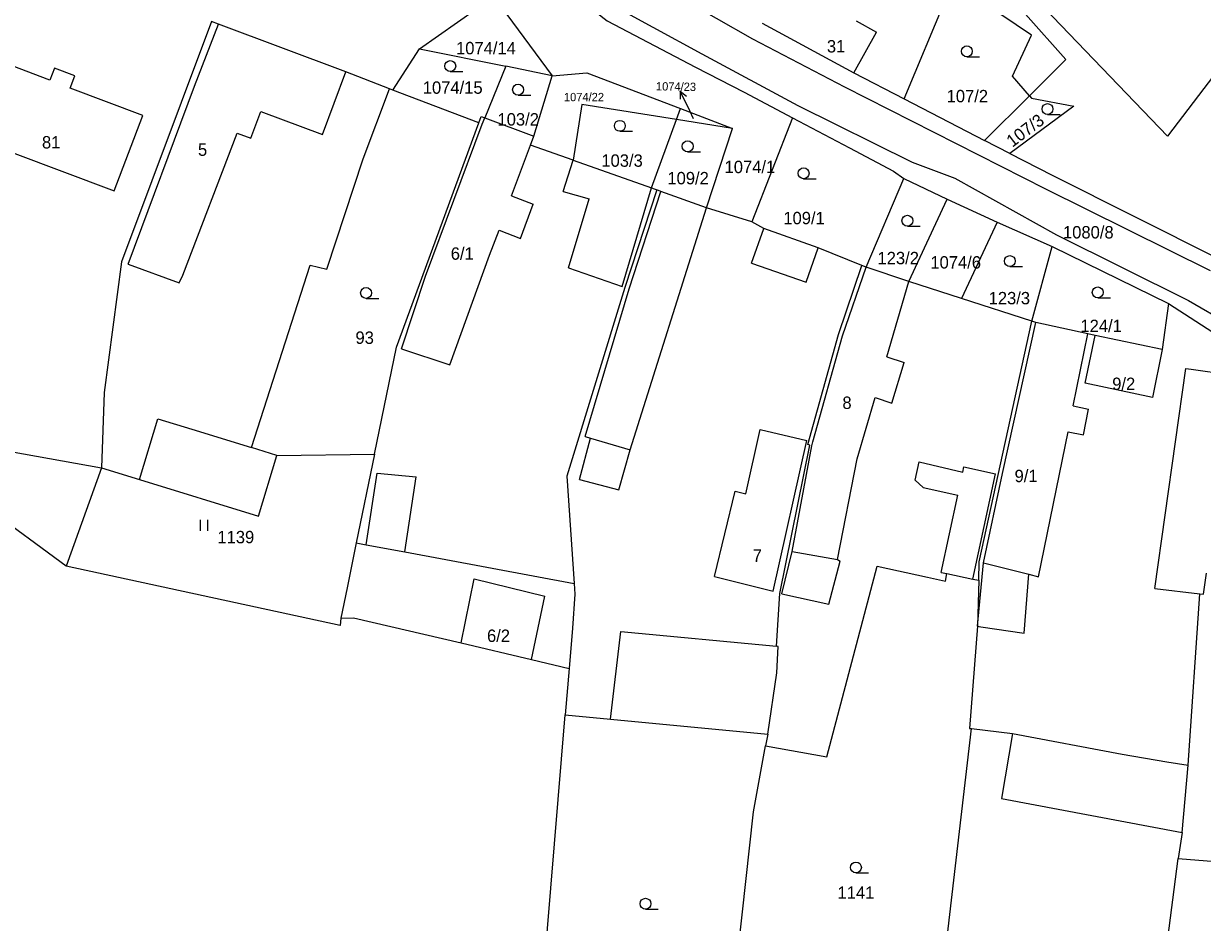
# Model space of a CAD drawing. Extents: x -746176 to -739709, y -1128407 to -1124482.
# Drawn here: x -742377 to -742215.1, y -1126240.2 to -1126116.8 of the extents above; entities that cross this region are included whole.
import ezdxf

# ---------------------------------------------------------------- set-up
doc = ezdxf.new("R2010")
doc.units = 0
for name, color, linetype in [('Hranice parcel', 7, 'Continuous'), ('Parcelní čísla', 7, 'Continuous'), ('Pop  PČ popisy', 7, 'Continuous'), ('Vnitřní kresba', 7, 'Continuous'), ('Značky kultur', 7, 'Continuous')]:
    doc.layers.add(name, color=color, linetype=linetype)

msp = doc.modelspace()

# ---------------------------------------------------------------- linework, layer by layer
at = {"layer": 'Hranice parcel'}
for p, q in [((-742256.06, -1126127.14), (-742249.36, -1126111.09)), ((-742326.25, -1126125.97), (-742322.59, -1126120.3)), ((-742322.59, -1126120.3), (-742310.73, -1126122.68)), ((-742310.73, -1126122.68), (-742313.65, -1126129.74)), ((-742304.4, -1126124.01), (-742310.73, -1126122.68)), ((-742233.84, -1126121.75), (-742238.85, -1126126.73)), ((-742306.9, -1126132.3), (-742304.4, -1126124.01)), ((-742238.85, -1126126.73), (-742241.16, -1126124.04)), ((-742326.25, -1126125.97), (-742326.7, -1126125.8)), ((-742314.45, -1126130.46), (-742326.25, -1126125.97)), ((-742256.06, -1126127.14), (-742245.01, -1126132.86)), ((-742245.01, -1126132.86), (-742238.85, -1126126.73)), ((-742238.85, -1126126.73), (-742238.56, -1126127.06)), ((-742300.31, -1126127.94), (-742301.49, -1126135.55)), ((-742287.33, -1126129.99), (-742300.31, -1126127.94)), ((-742287.33, -1126129.99), (-742286.78, -1126128.49)), ((-742286.78, -1126128.49), (-742279.63, -1126131.21)), ((-742313.65, -1126129.74), (-742306.9, -1126132.3)), ((-742290.74, -1126139.38), (-742287.33, -1126129.99)), ((-742279.63, -1126131.21), (-742287.33, -1126129.99)), ((-742271.38, -1126129.77), (-742276.96, -1126144.02)), ((-742283.2, -1126142.1), (-742279.63, -1126131.21)), ((-742241.52, -1126134.66), (-742245.01, -1126132.86)), ((-742301.49, -1126135.55), (-742290.74, -1126139.38)), ((-742261.26, -1126150.24), (-742256.1, -1126138.11)), ((-742256.1, -1126138.11), (-742250.15, -1126140.92)), ((-742290.74, -1126139.38), (-742290.03, -1126139.66)), ((-742276.96, -1126144.02), (-742283.2, -1126142.1)), ((-742255.42, -1126152.21), (-742250.15, -1126140.92)), ((-742250.15, -1126140.92), (-742243.28, -1126144.09)), ((-742243.28, -1126144.09), (-742248.16, -1126154.55)), ((-742243.28, -1126144.09), (-742235.72, -1126147.41)), ((-742238.52, -1126157.67), (-742235.72, -1126147.41)), ((-742235.72, -1126147.41), (-742219.77, -1126155.24)), ((-742261.26, -1126150.24), (-742261.84, -1126150.05)), ((-742255.42, -1126152.21), (-742261.26, -1126150.24)), ((-742248.16, -1126154.55), (-742255.42, -1126152.21)), ((-742238.52, -1126157.67), (-742248.16, -1126154.55)), ((-742219.77, -1126155.24), (-742220.62, -1126161.55)), ((-742219.77, -1126155.24), (-742210.43, -1126161.29)), ((-742220.62, -1126161.55), (-742229.8, -1126159.63)), ((-742408.55, -1126170.19), (-742366.28, -1126177.8)), ((-742342.18, -1126176.09), (-742328.77, -1126175.93)), ((-742328.77, -1126175.93), (-742331.28, -1126188.11)), ((-742366.28, -1126177.8), (-742371.13, -1126191.3)), ((-742331.28, -1126188.11), (-742332.55, -1126194.28)), ((-742332.55, -1126194.28), (-742333.4, -1126198.44)), ((-742302.07, -1126205.33), (-742302.59, -1126211.7)), ((-742274.79, -1126214.34), (-742275.09, -1126215.95)), ((-742253.45, -1126270.36), (-742246.8, -1126213.59)), ((-742217.86, -1126227.84), (-742218.41, -1126231.43)), ((-742226.78, -1126295.24), (-742218.41, -1126231.43)), ((-742218.41, -1126231.43), (-742213.31, -1126231.82))]:
    msp.add_line(p, q, dxfattribs=at)
for points in [[(-742322.88, -1126080.92), (-742314.75, -1126099.48), (-742306.74, -1126108.67), (-742296.81, -1126116.44), (-742284.71, -1126122.79), (-742278, -1126126.23), (-742271.38, -1126129.77)], [(-742226.91, -1126088.92), (-742220.21, -1126088.74), (-742209.67, -1126089.51), (-742205.42, -1126090.21), (-742203.87, -1126091.46), (-742201.62, -1126095.17), (-742208.44, -1126114.62), (-742212.86, -1126123.04), (-742219.9, -1126132.27), (-742250.27, -1126100.63), (-742249.53, -1126099.74), (-742247.13, -1126097.23), (-742241.64, -1126096.04), (-742237.53, -1126090.17), (-742226.91, -1126088.92)], [(-742253.64, -1126102.41), (-742239.39, -1126115.53), (-742233.84, -1126121.75)], [(-742241.16, -1126124.04), (-742238.58, -1126118.41), (-742249.36, -1126111.09)], [(-742322.59, -1126120.3), (-742314.77, -1126114.82), (-742311.38, -1126114.53), (-742304.4, -1126124.01)], [(-742351.14, -1126116.55), (-742363.54, -1126149.51), (-742365.92, -1126167.47), (-742366.28, -1126177.8)], [(-742326.7, -1126125.8), (-742332.7, -1126123.44), (-742350.2, -1126116.9), (-742351.14, -1126116.55)], [(-742275.57, -1126116.75), (-742262.95, -1126123.57), (-742256.06, -1126127.14)], [(-742360.61, -1126129.44), (-742370.56, -1126125.67), (-742369.93, -1126124), (-742372.74, -1126122.95), (-742373.37, -1126124.6), (-742381.46, -1126121.54), (-742385.41, -1126131.94), (-742364.54, -1126139.8), (-742360.61, -1126129.44)], [(-742304.4, -1126124.01), (-742299.64, -1126123.59), (-742286.78, -1126128.49)], [(-742342.18, -1126176.09), (-742345.69, -1126175.02), (-742337.62, -1126150), (-742335.33, -1126150.55), (-742330.35, -1126135.4), (-742326.7, -1126125.8)], [(-742238.56, -1126127.06), (-742232.76, -1126128.14), (-742241.52, -1126134.66)], [(-742328.77, -1126175.93), (-742325.75, -1126161.24), (-742314.45, -1126130.46)], [(-742314.45, -1126130.46), (-742314.12, -1126129.57), (-742313.65, -1126129.74)], [(-742271.38, -1126129.77), (-742263.55, -1126133.89), (-742257.51, -1126137.07), (-742256.1, -1126138.11)], [(-742301.49, -1126135.55), (-742307.36, -1126133.52), (-742306.9, -1126132.3)], [(-742241.52, -1126134.66), (-742235.74, -1126137.65), (-742212.93, -1126149.05), (-742177.34, -1126171.16)], [(-742290.03, -1126139.66), (-742294.39, -1126153.07), (-742302.36, -1126178.95), (-742301.38, -1126193.67)], [(-742283.2, -1126142.1), (-742289.47, -1126139.88), (-742290.03, -1126139.66)], [(-742261.84, -1126150.05), (-742267.85, -1126147.6), (-742275.32, -1126144.93), (-742276.96, -1126144.02)], [(-742274.79, -1126214.34), (-742273.54, -1126205.94), (-742273.34, -1126202.32), (-742273.6, -1126202.3), (-742273.12, -1126195.05), (-742269.02, -1126174.69), (-742269.3, -1126174.61), (-742265.06, -1126159.49), (-742261.84, -1126150.05)], [(-742245.81, -1126193.24), (-742245.74, -1126190.69), (-742238.52, -1126157.67)], [(-742229.8, -1126159.63), (-742230.81, -1126159.4), (-742237.95, -1126157.86), (-742238.52, -1126157.67)], [(-742220.62, -1126161.55), (-742221.93, -1126168.17), (-742231.21, -1126166.16), (-742229.8, -1126159.63)], [(-742366.28, -1126177.8), (-742361.05, -1126179.41), (-742344.7, -1126184.42), (-742342.18, -1126176.09)], [(-742371.13, -1126191.3), (-742382.1, -1126183.23), (-742395.78, -1126181.85), (-742403.65, -1126182.31), (-742424.12, -1126188.09), (-742455.22, -1126201.03)], [(-742331.28, -1126188.11), (-742329.94, -1126188.36), (-742324.62, -1126189.35), (-742301.38, -1126193.67)], [(-742333.4, -1126198.44), (-742333.49, -1126199.45), (-742371.13, -1126191.3)], [(-742275.09, -1126215.95), (-742266.66, -1126217.47), (-742260.87, -1126195.48), (-742259.76, -1126191.3), (-742252.85, -1126192.83), (-742250.39, -1126193.38), (-742250.2, -1126192.33), (-742246.63, -1126193.07), (-742245.81, -1126193.24)], [(-742217.86, -1126227.84), (-742217.03, -1126218.63), (-742215.44, -1126195.1), (-742214.95, -1126195.15), (-742214.53, -1126192.26)], [(-742301.38, -1126193.67), (-742301.28, -1126195.16), (-742301.61, -1126199.8), (-742302.07, -1126205.33)], [(-742245.81, -1126193.24), (-742245.98, -1126199.54), (-742247.06, -1126213.57), (-742246.8, -1126213.59)], [(-742333.4, -1126198.44), (-742331.66, -1126198.39), (-742316.87, -1126201.82), (-742307.21, -1126204.11), (-742302.07, -1126205.33)], [(-742281.72, -1126273.18), (-742307.41, -1126266.17), (-742306.81, -1126260.62), (-742305.51, -1126247.12), (-742302.59, -1126211.7)], [(-742302.59, -1126211.7), (-742296.36, -1126212.29), (-742274.79, -1126214.34)], [(-742246.8, -1126213.59), (-742241.16, -1126214.28), (-742242.7, -1126223.21), (-742217.86, -1126227.84)], [(-742281.72, -1126273.18), (-742280.8, -1126262.02), (-742276.72, -1126225.02), (-742275.09, -1126215.95)]]:
    msp.add_lwpolyline(points, dxfattribs=at)
at = {"layer": 'Pop  PČ popisy'}
for p, q in [((-742286.81, -1126126.09), (-742286.82, -1126127.21)), ((-742285.49, -1126128.79), (-742286.81, -1126126.09)), ((-742286.81, -1126126.09), (-742285.92, -1126126.77)), ((-742284.96, -1126129.91), (-742285.49, -1126128.79))]:
    msp.add_line(p, q, dxfattribs=at)
at = {"layer": 'Vnitřní kresba'}
for p, q in [((-742296.2, -1126107.89), (-742276.88, -1126118.92)), ((-742297.3, -1126113.67), (-742283.82, -1126120.97)), ((-742353.49, -1126125.42), (-742350.2, -1126116.9)), ((-742262.66, -1126116.47), (-742259.87, -1126118.01)), ((-742276.88, -1126118.92), (-742264.25, -1126125.49)), ((-742262.95, -1126123.57), (-742259.87, -1126118.01)), ((-742283.82, -1126120.97), (-742270.64, -1126128.09)), ((-742335.92, -1126132.03), (-742332.7, -1126123.44)), ((-742362.62, -1126149.84), (-742353.49, -1126125.42)), ((-742264.25, -1126125.49), (-742236.63, -1126139.49)), ((-742345.76, -1126132.56), (-742344.4, -1126128.89)), ((-742344.4, -1126128.89), (-742335.92, -1126132.03)), ((-742270.64, -1126128.09), (-742254.96, -1126135.85)), ((-742321.76, -1126151.49), (-742313.99, -1126130.63)), ((-742313.99, -1126130.63), (-742313.65, -1126129.74)), ((-742355.11, -1126151.35), (-742347.65, -1126131.87)), ((-742347.65, -1126131.87), (-742345.76, -1126132.56)), ((-742309.98, -1126140.49), (-742307.36, -1126133.52)), ((-742302.87, -1126139.86), (-742301.49, -1126135.55)), ((-742254.96, -1126135.85), (-742249.1, -1126138.06)), ((-742249.1, -1126138.06), (-742235.14, -1126145.83)), ((-742309.98, -1126140.49), (-742306.99, -1126141.62)), ((-742302.87, -1126139.86), (-742299.31, -1126140.9)), ((-742294.78, -1126152.93), (-742290.74, -1126139.38)), ((-742293.82, -1126153.25), (-742289.47, -1126139.88)), ((-742236.63, -1126139.49), (-742214.05, -1126150.74)), ((-742308.71, -1126146.33), (-742306.99, -1126141.62)), ((-742302.15, -1126150.33), (-742299.31, -1126140.9)), ((-742293.68, -1126175.34), (-742283.2, -1126142.1)), ((-742312.98, -1126148.6), (-742311.68, -1126145.17)), ((-742311.68, -1126145.17), (-742308.71, -1126146.33)), ((-742277.02, -1126149.7), (-742275.32, -1126144.93)), ((-742235.14, -1126145.83), (-742216.99, -1126154.85)), ((-742318.44, -1126163.68), (-742312.98, -1126148.6)), ((-742269.51, -1126152.34), (-742267.85, -1126147.6)), ((-742362.62, -1126149.84), (-742355.61, -1126152.4)), ((-742302.15, -1126150.33), (-742294.78, -1126152.93)), ((-742277.02, -1126149.7), (-742269.51, -1126152.34)), ((-742264.5, -1126159.68), (-742261.26, -1126150.24)), ((-742355.61, -1126152.4), (-742355.11, -1126151.35)), ((-742325.07, -1126161.47), (-742321.76, -1126151.49)), ((-742299.86, -1126173.52), (-742293.82, -1126153.25)), ((-742258.44, -1126162.59), (-742255.42, -1126152.21)), ((-742216.99, -1126154.85), (-742209.7, -1126159.09)), ((-742242.53, -1126178.6), (-742237.95, -1126157.86)), ((-742268.58, -1126174.24), (-742264.5, -1126159.68)), ((-742232.86, -1126169.31), (-742230.81, -1126159.4)), ((-742325.07, -1126161.47), (-742318.44, -1126163.68)), ((-742258.44, -1126162.59), (-742256.05, -1126163.36)), ((-742257.72, -1126168.93), (-742256.05, -1126163.36)), ((-742221.64, -1126194.36), (-742217.39, -1126164.16)), ((-742217.39, -1126164.16), (-742216.66, -1126164.27)), ((-742216.66, -1126164.27), (-742211.41, -1126165.02)), ((-742262.5, -1126176.58), (-742260.05, -1126168.17)), ((-742260.05, -1126168.17), (-742257.72, -1126168.93)), ((-742232.86, -1126169.31), (-742230.73, -1126169.75)), ((-742231.44, -1126173.28), (-742230.73, -1126169.75)), ((-742361.05, -1126179.41), (-742358.51, -1126171.1)), ((-742358.51, -1126171.1), (-742353.86, -1126172.49)), ((-742353.86, -1126172.49), (-742345.69, -1126175.02)), ((-742277.79, -1126181.37), (-742275.84, -1126172.55)), ((-742275.84, -1126172.55), (-742269.42, -1126174.05)), ((-742237.59, -1126192.75), (-742233.53, -1126172.88)), ((-742233.53, -1126172.88), (-742231.44, -1126173.28)), ((-742300.61, -1126179.42), (-742299.11, -1126173.74)), ((-742299.86, -1126173.52), (-742299.11, -1126173.74)), ((-742299.11, -1126173.74), (-742293.68, -1126175.34)), ((-742274.02, -1126194.74), (-742269.42, -1126174.05)), ((-742268.73, -1126174.77), (-742268.58, -1126174.24)), ((-742295.23, -1126180.82), (-742293.68, -1126175.34)), ((-742271.45, -1126189.28), (-742268.73, -1126174.77)), ((-742265.2, -1126190.4), (-742262.5, -1126176.58)), ((-742254.53, -1126179.5), (-742254.01, -1126176.99)), ((-742254.01, -1126176.99), (-742248, -1126178.41)), ((-742248, -1126178.41), (-742247.84, -1126177.67)), ((-742247.84, -1126177.67), (-742243.51, -1126178.62)), ((-742329.94, -1126188.36), (-742328.41, -1126178.52)), ((-742328.41, -1126178.52), (-742323.05, -1126179.05)), ((-742324.62, -1126189.35), (-742323.05, -1126179.05)), ((-742300.61, -1126179.42), (-742295.23, -1126180.82)), ((-742246.63, -1126193.07), (-742243.51, -1126178.62)), ((-742245.16, -1126190.83), (-742242.53, -1126178.6)), ((-742282.11, -1126192.72), (-742279.25, -1126181.03)), ((-742279.25, -1126181.03), (-742277.79, -1126181.37)), ((-742254.53, -1126179.5), (-742253.42, -1126180.51)), ((-742253.42, -1126180.51), (-742248.68, -1126181.54)), ((-742250.98, -1126192.17), (-742248.68, -1126181.54)), ((-742272.83, -1126195.11), (-742271.45, -1126189.28)), ((-742271.45, -1126189.28), (-742265.2, -1126190.4)), ((-742266.38, -1126196.53), (-742264.83, -1126190.6)), ((-742265.2, -1126190.4), (-742264.83, -1126190.6)), ((-742250.98, -1126192.17), (-742250.2, -1126192.33)), ((-742245.98, -1126199.54), (-742245.16, -1126190.83)), ((-742245.16, -1126190.83), (-742238.94, -1126192.41)), ((-742239.56, -1126200.52), (-742238.94, -1126192.41)), ((-742238.94, -1126192.41), (-742237.59, -1126192.75)), ((-742316.87, -1126201.82), (-742315.09, -1126193.06)), ((-742315.09, -1126193.06), (-742305.41, -1126195.41)), ((-742282.11, -1126192.72), (-742274.02, -1126194.74)), ((-742307.21, -1126204.11), (-742305.41, -1126195.41)), ((-742272.83, -1126195.11), (-742266.38, -1126196.53)), ((-742221.64, -1126194.36), (-742215.44, -1126195.1)), ((-742296.36, -1126212.29), (-742294.97, -1126200.25)), ((-742294.97, -1126200.25), (-742273.6, -1126202.3)), ((-742245.98, -1126199.54), (-742245.51, -1126199.61)), ((-742245.51, -1126199.61), (-742239.56, -1126200.52)), ((-742241.16, -1126214.28), (-742226.13, -1126217.11)), ((-742226.13, -1126217.11), (-742220, -1126218.18)), ((-742220, -1126218.18), (-742217.03, -1126218.63))]:
    msp.add_line(p, q, dxfattribs=at)
at = {"layer": 'Značky kultur'}
for p, q in [((-742247.44, -1126121.38), (-742245.69, -1126121.38)), ((-742318.38, -1126123.41), (-742316.63, -1126123.41)), ((-742309.07, -1126126.65), (-742307.32, -1126126.65)), ((-742236.37, -1126129.31), (-742234.62, -1126129.31)), ((-742295.09, -1126131.61), (-742293.34, -1126131.61)), ((-742285.78, -1126134.42), (-742284.03, -1126134.42)), ((-742269.86, -1126138.12), (-742268.11, -1126138.12)), ((-742255.6, -1126144.64), (-742253.85, -1126144.64)), ((-742241.54, -1126150.17), (-742239.79, -1126150.17)), ((-742329.94, -1126154.54), (-742328.19, -1126154.54)), ((-742229.47, -1126154.48), (-742227.72, -1126154.48)), ((-742352.65, -1126186.46), (-742352.65, -1126184.96)), ((-742351.65, -1126186.46), (-742351.65, -1126184.96)), ((-742262.68, -1126233.41), (-742260.93, -1126233.41)), ((-742291.57, -1126238.39), (-742289.82, -1126238.39))]:
    msp.add_line(p, q, dxfattribs=at)
for centre in [(-742247.44, -1126120.63), (-742318.38, -1126122.66), (-742309.07, -1126125.9), (-742236.37, -1126128.56), (-742295.09, -1126130.86), (-742285.78, -1126133.67), (-742269.86, -1126137.37), (-742255.6, -1126143.89), (-742241.54, -1126149.42), (-742329.94, -1126153.79), (-742229.47, -1126153.73), (-742262.68, -1126232.66), (-742291.57, -1126237.64)]:
    msp.add_circle(centre, 0.75, dxfattribs=at)

# ---------------------------------------------------------------- texts
at = {"layer": 'Parcelní čísla'}
for s, height, p in [('1074/14', 1.7, (-742317.58, -1126121.04)), ('31', 1.7, (-742266.66, -1126120.79)), ('1074/15', 1.7, (-742322.15, -1126126.46)), ('107/2', 1.7, (-742250.22, -1126127.63)), ('1074/22', 1.139, (-742302.77, -1126127.48)), ('103/2', 1.7, (-742311.89, -1126130.82)), ('81', 1.7, (-742374.44, -1126133.97)), ('5', 1.7, (-742353.02, -1126134.98)), ('103/3', 1.7, (-742297.63, -1126136.48)), ('1074/1', 1.7, (-742280.71, -1126137.35)), ('109/2', 1.7, (-742288.56, -1126138.89)), ('109/1', 1.7, (-742272.64, -1126144.37)), ('1080/8', 1.7, (-742234.24, -1126146.32)), ('6/1', 1.7, (-742318.31, -1126149.24)), ('123/2', 1.7, (-742259.71, -1126149.86)), ('1074/6', 1.7, (-742252.45, -1126150.45)), ('123/3', 1.7, (-742244.45, -1126155.36)), ('124/1', 1.7, (-742231.85, -1126159.17)), ('93', 1.7, (-742331.39, -1126160.79)), ('9/2', 1.7, (-742227.48, -1126167.12)), ('8', 1.7, (-742264.53, -1126169.72)), ('9/1', 1.7, (-742240.89, -1126179.77)), ('1139', 1.7, (-742350.35, -1126188.16)), ('7', 1.7, (-742276.85, -1126190.71)), ('6/2', 1.7, (-742313.33, -1126201.7)), ('1141', 1.7, (-742265.2, -1126236.96))]:
    msp.add_text(s, height=height, dxfattribs=at).set_placement(p)
for s, height, rotation, p in [('1074/23', 1.139, 359, (-742290.14, -1126125.99)), ('107/3', 1.7, 37, (-742241.2, -1126133.88))]:
    msp.add_text(s, height=height, rotation=rotation, dxfattribs=at).set_placement(p)

doc.saveas('drawing.dxf')
